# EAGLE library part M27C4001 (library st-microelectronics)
4 Mbit (512Kb x 8) UV EPROM and OTP EPROM Source: www.st.com .. M27C4001 EPROM 4 MBIT.pdf
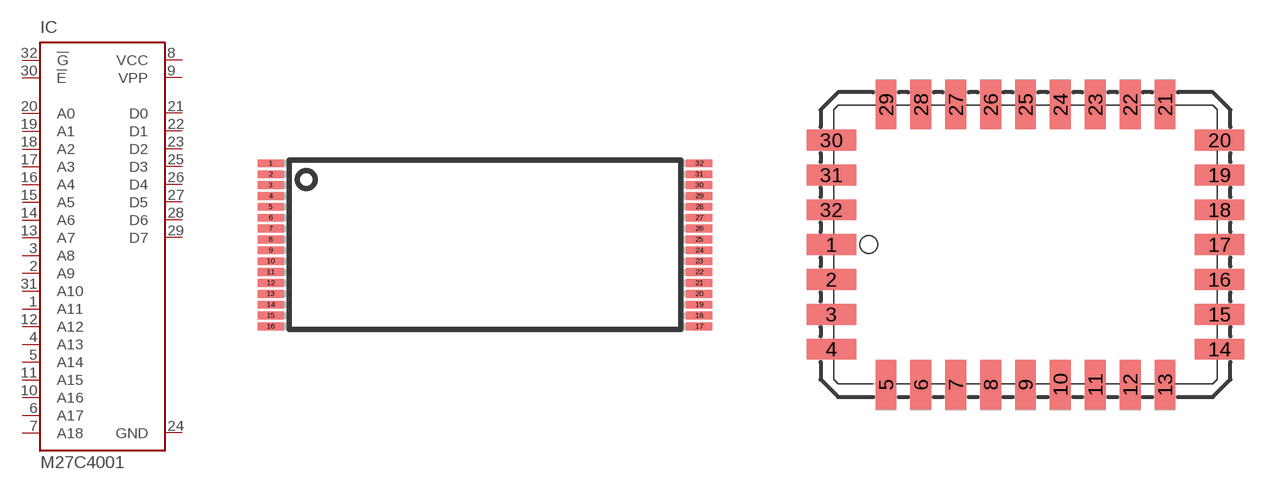
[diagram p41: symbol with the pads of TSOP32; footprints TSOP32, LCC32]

Designator prefix IC

## M27C4001N (OC_FARNELL: unknown; OC_NEWARK: unknown)  [TSOP32]
1  A11  in
2  A9  in
3  A8  in
4  A13  in
5  A14  in
6  A17  in
7  A18  in
8  VCC  pwr
9  VPP  pwr
10  A16  in
11  A15  in
12  A12  in
13  A7  in
14  A6  in
15  A5  in
16  A4  in
17  A3  in
18  A2  in
19  A1  in
20  A0  in
21  D0  hiz
22  D1  hiz
23  D2  hiz
24  GND  pwr
25  D3  hiz
26  D4  hiz
27  D5  hiz
28  D6  hiz
29  D7  hiz
30  !E  in
31  A10  in
32  !G  in

## M27C4001C (MPN: M27C4001-10C1; OC_FARNELL: 1094260; OC_NEWARK: 24M5086)  [LCC32]
1  VPP  pwr
2  A16  in
3  A15  in
4  A12  in
5  A7  in
6  A6  in
7  A5  in
8  A4  in
9  A3  in
10  A2  in
11  A1  in
12  A0  in
13  D0  hiz
14  D1  hiz
15  D2  hiz
16  GND  pwr
17  D3  hiz
18  D4  hiz
19  D5  hiz
20  D6  hiz
21  D7  hiz
22  !E  in
23  A10  in
24  !G  in
25  A11  in
26  A9  in
27  A8  in
28  A13  in
29  A14  in
30  A17  in
31  A18  in
32  VCC  pwr

## M27C4001B (MPN: M27C4001-10B1; OC_FARNELL: 3338137; OC_NEWARK: 56P9200)  [DIL32]
Pads as for LCC32

## M27C4001F (MPN: M27C4001-15F1; OC_FARNELL: 1132004; OC_NEWARK: 24M5087)  [FDIP32]
Pads as for LCC32

## Footprint TSOP32 (pad centres in mm)
Thin Small Outline Package
smd 1.2 x 0.36: 1 -9.85,3.75; 2 -9.85,3.25; 3 -9.85,2.75; 4 -9.85,2.25; 5 -9.85,1.75; 6 -9.85,1.25; 7 -9.85,0.75; 8 -9.85,0.25; 9 -9.85,-0.25; 10 -9.85,-0.75; 11 -9.85,-1.25; 12 -9.85,-1.75; 13 -9.85,-2.25; 14 -9.85,-2.75; 15 -9.85,-3.25; 16 -9.85,-3.75; 17 9.85,-3.75; 18 9.85,-3.25; 19 9.85,-2.75; 20 9.85,-2.25; 21 9.85,-1.75; 22 9.85,-1.25; 23 9.85,-0.75; 24 9.85,-0.25; 25 9.85,0.25; 26 9.85,0.75; 27 9.85,1.25; 28 9.85,1.75; 29 9.85,2.25; 30 9.85,2.75; 31 9.85,3.25; 32 9.85,3.75

## Footprint LCC32 (pad centres in mm)
LEADED CHIP CARRIER rectangle
smd 1.8 x 0.76: 1 -7.07,0.635; 2 -7.07,-0.635; 3 -7.07,-1.905; 4 -7.07,-3.175; 14 7.07,-3.175; 15 7.07,-1.905; 16 7.07,-0.635; 17 7.07,0.635; 18 7.07,1.905; 19 7.07,3.175; 20 7.07,4.445; 30 -7.07,4.445; 31 -7.07,3.175; 32 -7.07,1.905
smd 0.76 x 1.8: 5 -5.08,-4.47; 6 -3.81,-4.47; 7 -2.54,-4.47; 8 -1.27,-4.47; 9 0,-4.47; 10 1.27,-4.47; 11 2.54,-4.47; 12 3.81,-4.47; 13 5.08,-4.47; 21 5.08,5.74; 22 3.81,5.74; 23 2.54,5.74; 24 1.27,5.74; 25 0,5.74; 26 -1.27,5.74; 27 -2.54,5.74; 28 -3.81,5.74; 29 -5.08,5.74

## Footprint DIL32 (pad centres in mm)
Dual In Line Package
drill 0.813 long: 1 -19.05,-7.62; 2 -16.51,-7.62; 3 -13.97,-7.62; 4 -11.43,-7.62; 5 -8.89,-7.62; 6 -6.35,-7.62; 7 -3.81,-7.62; 8 -1.27,-7.62; 9 1.27,-7.62; 10 3.81,-7.62; 11 6.35,-7.62; 12 8.89,-7.62; 13 11.43,-7.62; 14 13.97,-7.62; 15 16.51,-7.62; 16 19.05,-7.62; 17 19.05,7.62; 18 16.51,7.62; 19 13.97,7.62; 20 11.43,7.62; 21 8.89,7.62; 22 6.35,7.62; 23 3.81,7.62; 24 1.27,7.62; 25 -1.27,7.62; 26 -3.81,7.62; 27 -6.35,7.62; 28 -8.89,7.62; 29 -11.43,7.62; 30 -13.97,7.62; 31 -16.51,7.62; 32 -19.05,7.62

## Footprint FDIP32 (pad centres in mm)
FDIP32W (F) Source: www.st.com
drill 0.813 round: 1 -19.05,-7.62; 2 -16.51,-7.62; 3 -13.97,-7.62; 4 -11.43,-7.62; 5 -8.89,-7.62; 6 -6.35,-7.62; 7 -3.81,-7.62; 8 -1.27,-7.62; 9 1.27,-7.62; 10 3.81,-7.62; 11 6.35,-7.62; 12 8.89,-7.62; 13 11.43,-7.62; 14 13.97,-7.62; 15 16.51,-7.62; 16 19.05,-7.62; 17 19.05,7.62; 18 16.51,7.62; 19 13.97,7.62; 20 11.43,7.62; 21 8.89,7.62; 22 6.35,7.62; 23 3.81,7.62; 24 1.27,7.62; 25 -1.27,7.62; 26 -3.81,7.62; 27 -6.35,7.62; 28 -8.89,7.62; 29 -11.43,7.62; 30 -13.97,7.62; 31 -16.51,7.62; 32 -19.05,7.62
